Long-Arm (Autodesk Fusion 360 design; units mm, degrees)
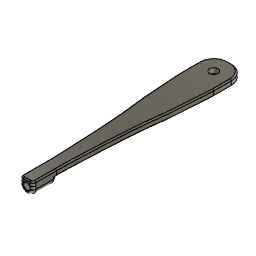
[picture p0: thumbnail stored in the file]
base_feature "Base Feature" bodies "Tube arm"
chamfer "Chamfer1" distance 0.8
named bodies: "Tube arm"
